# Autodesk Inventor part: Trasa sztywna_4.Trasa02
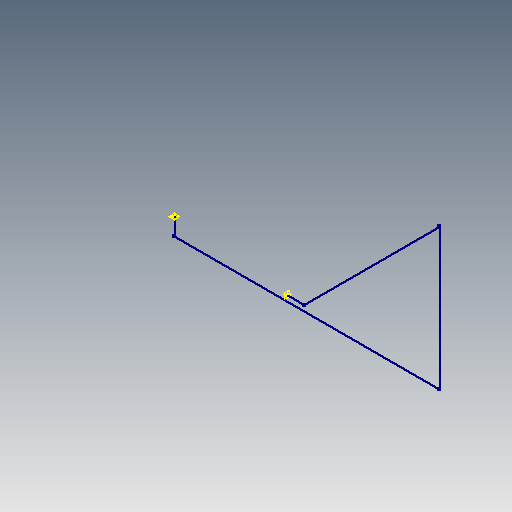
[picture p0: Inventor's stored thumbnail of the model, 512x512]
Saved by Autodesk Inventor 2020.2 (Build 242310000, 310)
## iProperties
StyleName: _Piping Style 52
Manager: www.cadconsulting.pl
Company: Fabian Stasiak CAD Consulting
_PSKETCH_SNAP: False
_PSKETCH_RSNP: False
_BASENETWORK_NOTAUTODIMENSION: False
Name: JIS G 3458/JIS B 2316 - Rury stalowe spawane i łączniki
ActiveState: True
PipeType: Rigid Pipe
Material: UnInitValue
Standard: UnInitValue
FittingMaterial: UnInitValue
FittingStandard: UnInitValue
RouteDirection90: True
RouteDirection45: True
IsFlanged: False
IsButtWelded: False
DiameterType: Nominal
Diameter: M40
Schedule: 80
OD: UnInitValue
ID: UnInitValue
Ending: UnInitValue
IntermediateSegmentsMin: 60,000 mm
IntermediateSegmentsMax: 5000,000 mm
IntermediateSegmentsInc: 1,000 mm
TerminationSegmentsMin: 60,000 mm
TerminationSegmentsMax: 5000,000 mm
TerminationSegmentsInc: 1,000 mm
RoundUpValue: UnInitValue
PipingComponentColor: As Material
PipeKey: v3#da14b0ab-0b36-4851-8d66-8c9cd0bcbe86#23
CouplingKey: v3#12b64993-10e6-4915-8315-0c0cce209ad0#8
Elbow90Key: v3#1f65ece3-c41a-48d4-8661-909ed34ade86#8
Elbow45Key: v3#28e76e79-e22c-40ab-8be2-ff545b1407c5#8
GasketKey: UnInitValue
FlangeKey: UnInitValue
_ComponentInfo: <CS><C N="Pipe" R="2.430000" IR="1.920000" PL="PL" PN="JIS G 3458 Pipe 40 A x Sch 80"><CO N="1"><FE V="0"/><FD V="1"/><ET V="Welded"/><NS V="M40"/><MA V="0.0000
Gap: UnInitValue
ShowGap: UnInitValue
MixedUnits: False
UseFlangsForCouplings: UnInitValue
IsSelfDraining: False
ElbowCustomKey: UnInitValue
Created: 2014-08
Part Number: Trasa sztywna_4.Trasa02
Material: Ogólny
Document SubType Name: Modeling
Designer: F.Stasiak
Density: 1 g/cm^3
Appearance: Domyślna
Catalog Web Link: www.expertbooks.pl
Author: F.Stasiak
Subject: Zbiór ćwiczeń. Autodesk Inventor 2020. Kurs Professional
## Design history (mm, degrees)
node "Punkt konstrukcyjny1"
node "Punkt konstrukcyjny2"
node "Płaszczyzna konstrukcyjna1"
node "Płaszczyzna konstrukcyjna2"
sketch "Szkic 3D1" dims "d0" = 150, "d1" = 150, "d2" = 150 (derived), "d4" = 1250 (derived), "d5" = 1200 (derived), "d6" = 150 (derived), "d10" = 2350 (derived)
